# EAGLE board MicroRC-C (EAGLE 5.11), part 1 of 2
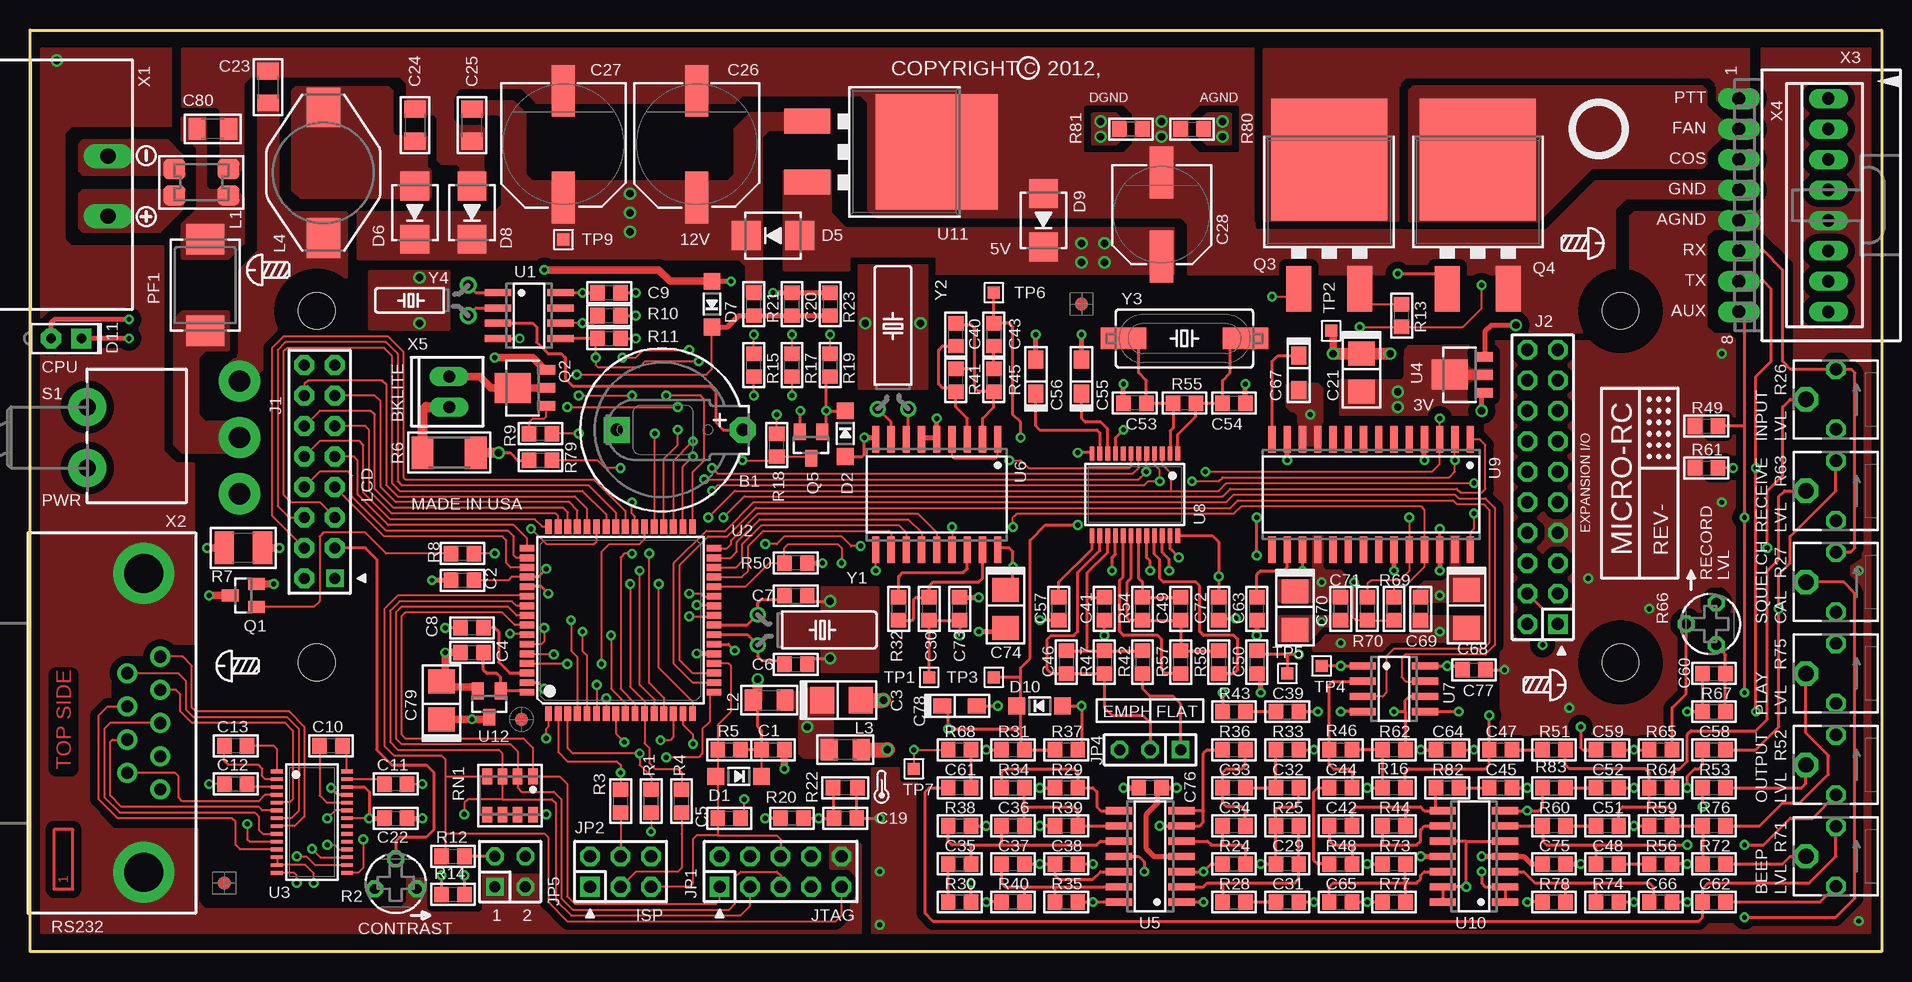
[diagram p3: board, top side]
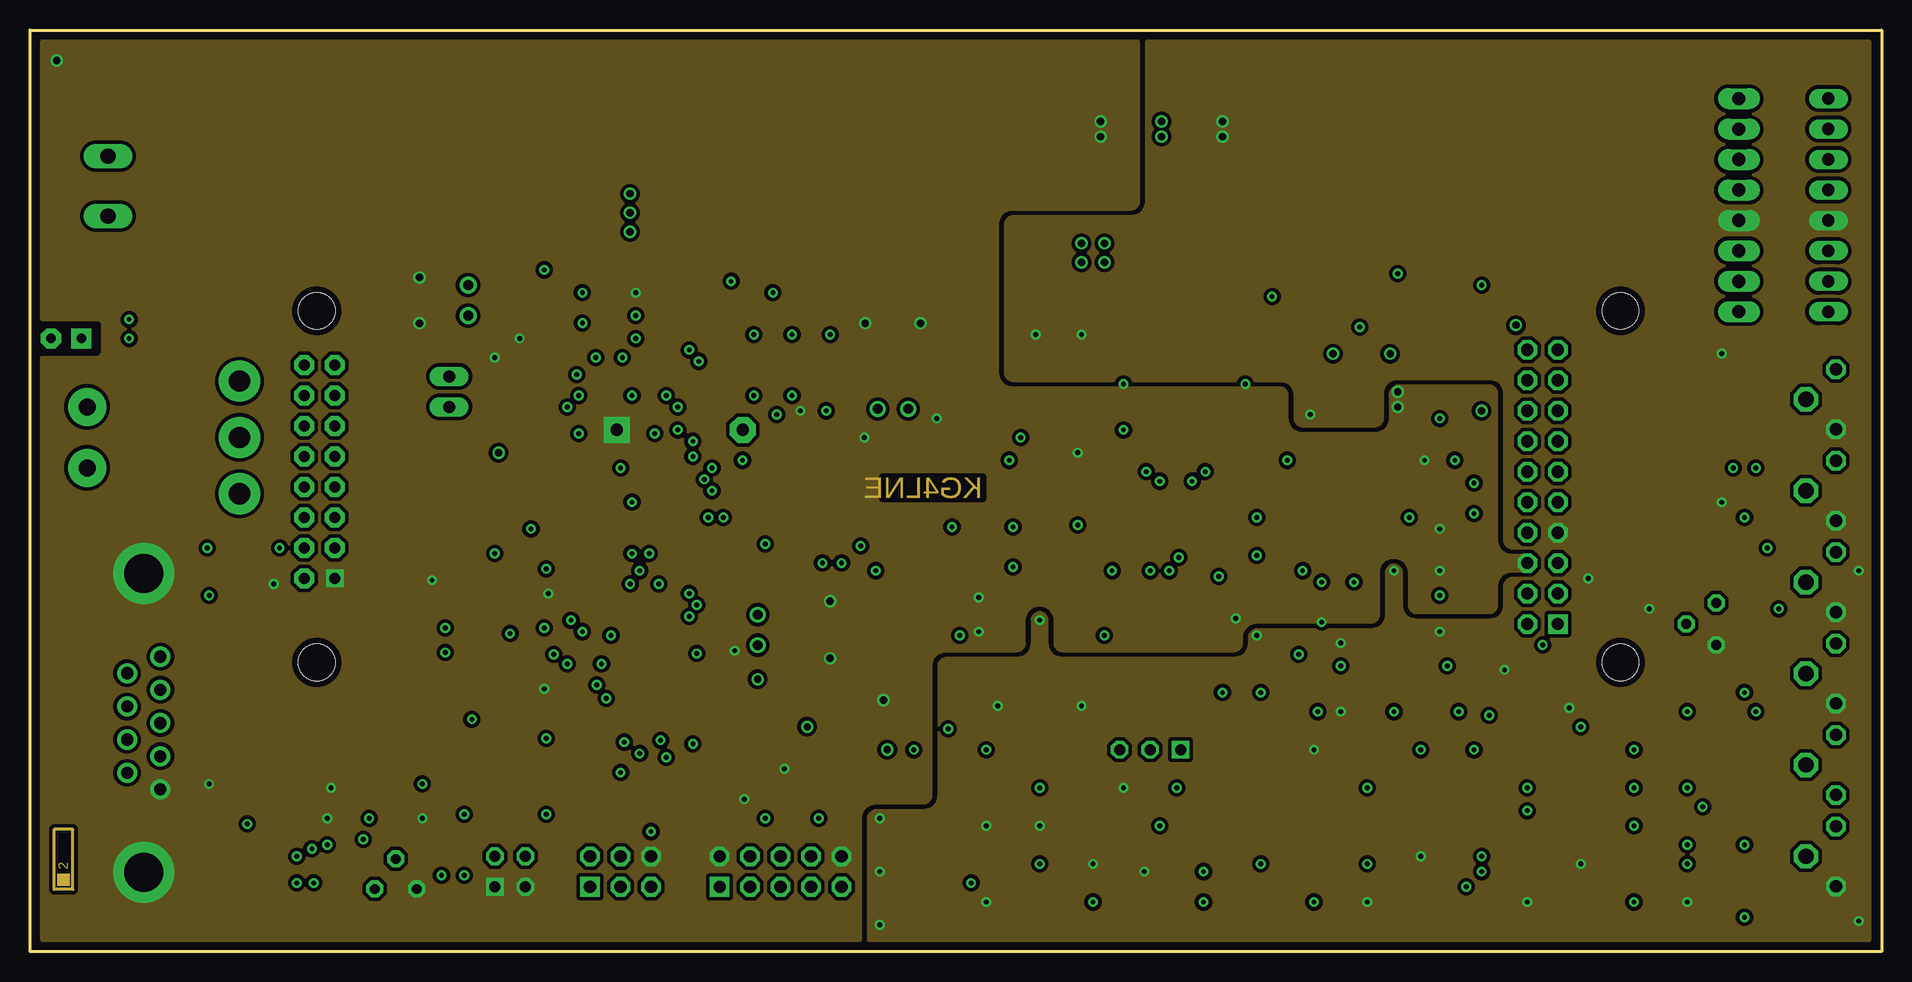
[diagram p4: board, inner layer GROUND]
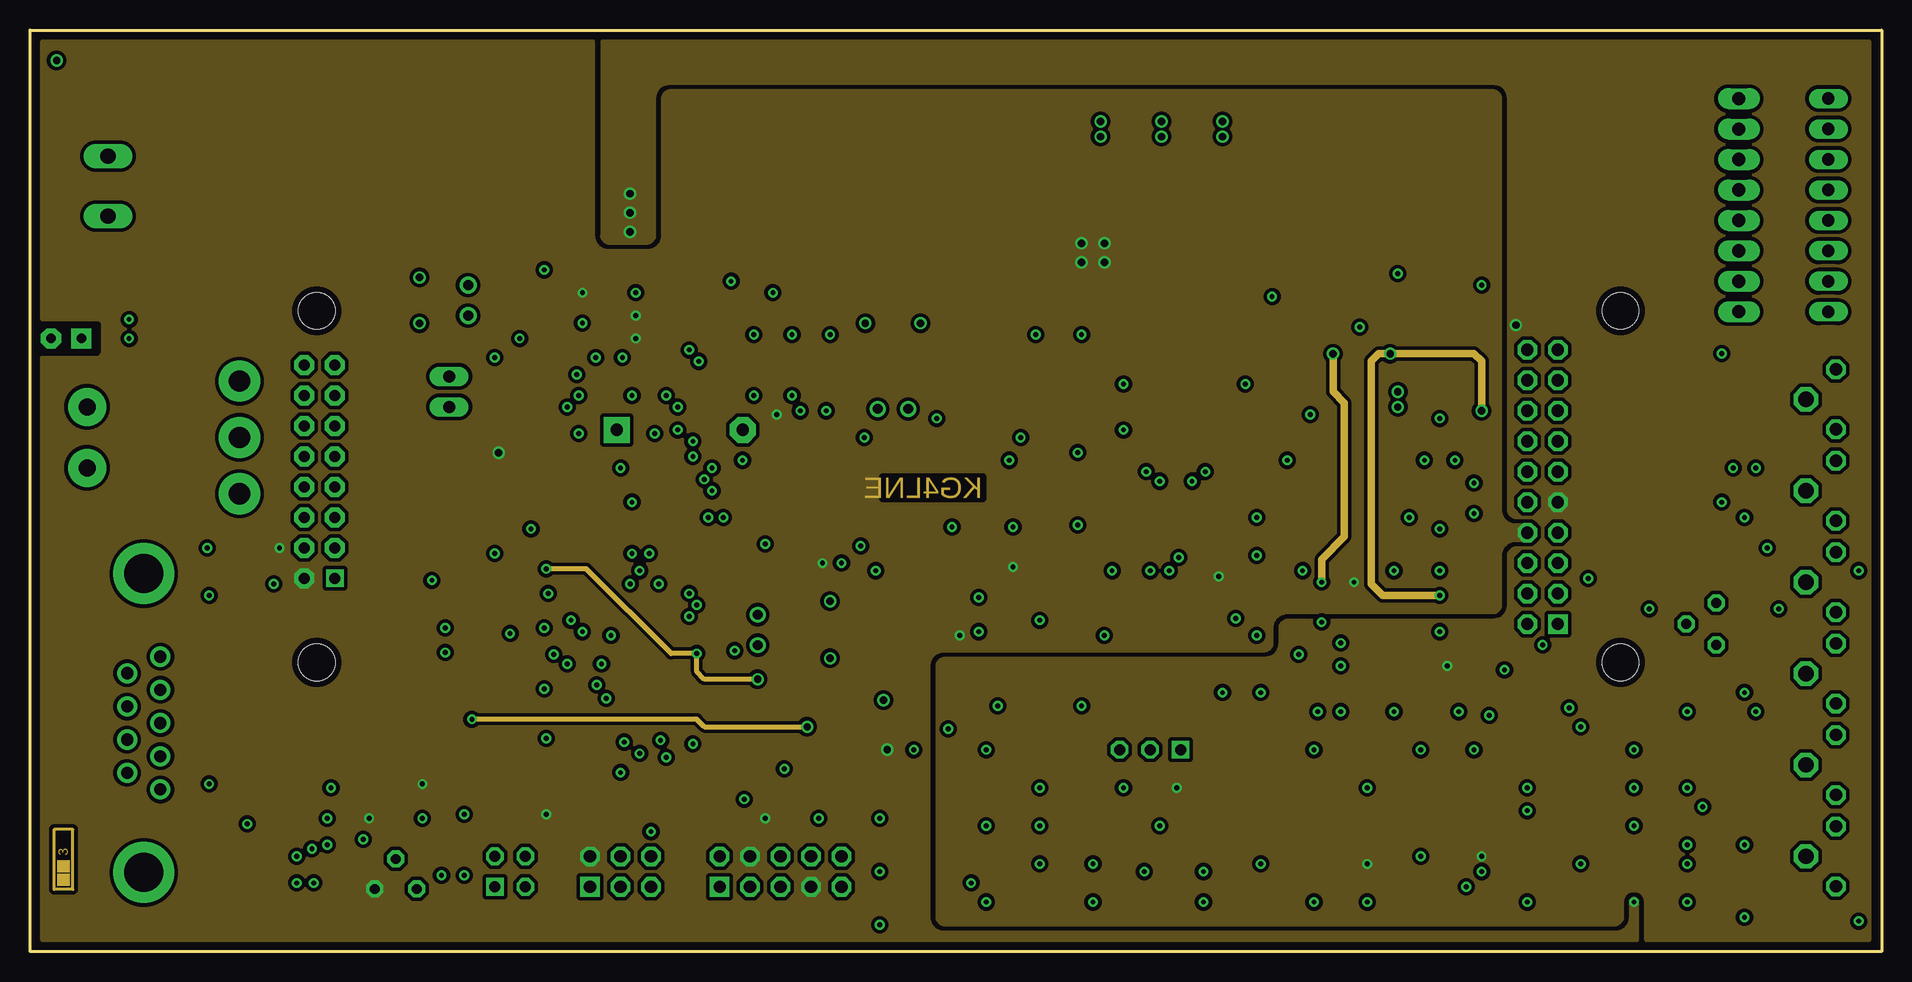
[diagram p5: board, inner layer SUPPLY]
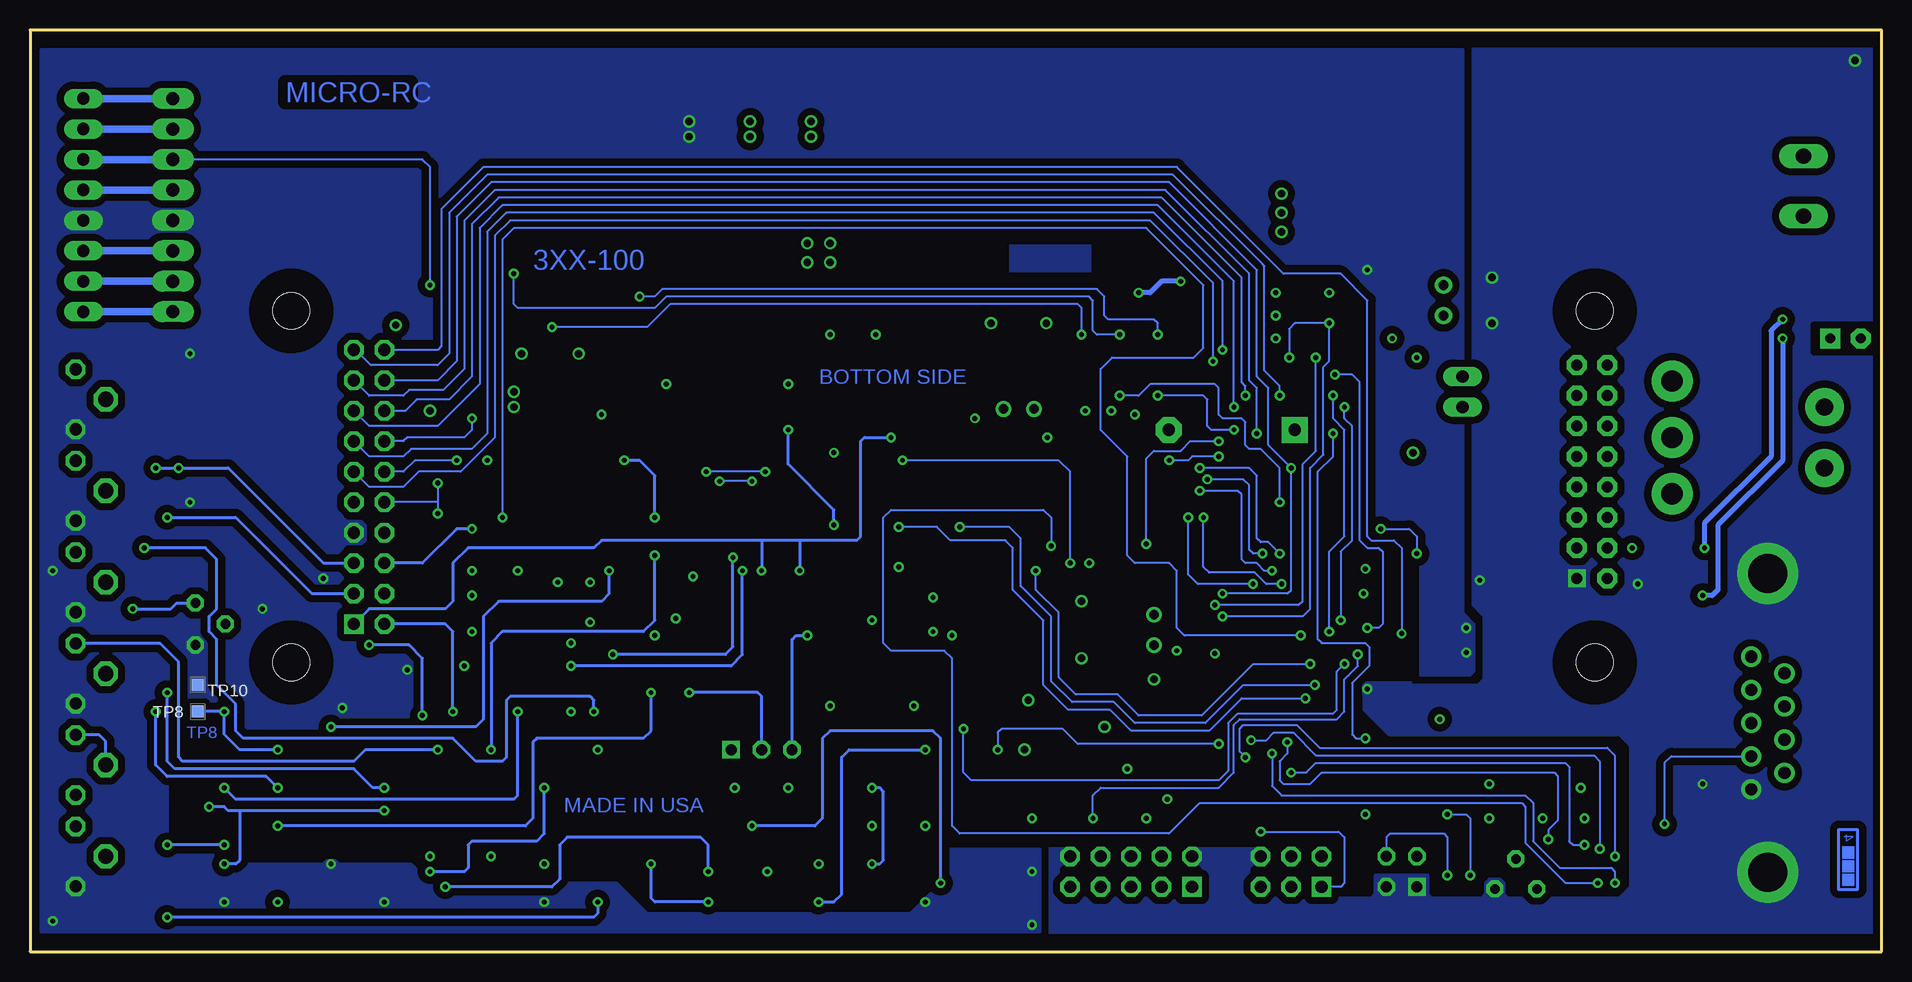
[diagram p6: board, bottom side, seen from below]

Size 154.31 x 76.83 mm. Coordinates in mm from the lower left corner, seen from the top.
Outline: 0,76.83 154.31,76.83 154.31,0 0,0 0,76.83
Copper layers (1*2+3*16): Top 0.035mm / dielectric 0.36mm / GROUND 0.035mm / dielectric 0.71mm / SUPPLY 0.035mm / dielectric 0.36mm / Bottom 0.035mm
Design rules "PRD_SN": minimum track width 2mil, minimum drill 16mil, track to track 8mil, track to pad 8mil, pad to pad 8mil, via to via 8mil, smd to smd 8mil, copper to edge 20mil, drill to drill 8mil, minimum pad ring 10mil, minimum via ring 8mil, stop-mask expansion 4mil, vias tented up to drill 32mil, thermal gap 24mil
Holes 0.41 mm at 198.11,50.4
Holes 0.61 mm at 198.11,45.32
Holes 0.81 mm at 198.11,40.24
Holes 0.91 mm at 198.11,35.16
Holes 1.02 mm at 198.11,30.08
Holes 1.09 mm at 198.11,25
Holes 1.27 mm at 198.11,19.92
Holes 1.42 mm at 198.11,14.84
Holes 1.78 mm at 198.11,9.76
Holes 3.05 mm at 198.11,4.68

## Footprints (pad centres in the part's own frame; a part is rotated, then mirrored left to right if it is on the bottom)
BR1225 = drill 1.016 pad 2.159 octagon: + 5.75,0 | drill 1.016 pad 2.159 square: - -4.75,0
C0805 = smd 1.2 x 1.3: 1 -0.953,0; 2 0.953,0
C3528/T = smd 2 x 2.2: + 1.587,0; - -1.587,0
C1206 = smd 1.4 x 1.8: 1 -1.329,0; 2 1.329,0
CSV-G = smd 4.318 x 1.93: + -4.445,0; - 4.445,0
CSV-E/F = smd 4.318 x 1.93: + -3.493,0; - 3.493,0
C3216/T = smd 1.5 x 1.27: + 1.429,0; - -1.429,0
SOD123 = smd 1.4 x 1.4: A 1.905,0; C -1.905,0
SMB = smd 2.4 x 2.4: A 2.223,0; C -2.223,0
LED535 = drill 0.813 pad 1.676 octagon: A -1.27,0 | drill 0.813 pad 1.676 square: K 1.27,0
DMC20261 = drill 0.914 pad 1.422 square: 1 2.54,-7.62 | drill 0.914 pad 1.676 octagon: 2 0,-7.62; 3 2.54,-5.08; 4 0,-5.08; 5 2.54,-2.54; 6 0,-2.54; 7 2.54,0; 8 0,0; 9 2.54,2.54; 10 0,2.54; 11 2.54,5.08; 12 0,5.08; 13 2.54,7.62; 14 0,7.62; 15 2.54,10.16; 16 0,10.16 | hole 3.048: 1.039,14.683; 1.039,-14.635; 109.674,-14.635; 109.674,14.682
MA10-2 = drill 1.016 square: 1 -11.43,-1.27 | drill 1.016 octagon: 2 -11.43,1.27; 3 -8.89,-1.27; 4 -8.89,1.27; 5 -6.35,-1.27; 6 -6.35,1.27; 7 -3.81,-1.27; 8 -3.81,1.27; 9 -1.27,-1.27; 10 -1.27,1.27; 11 1.27,-1.27; 12 1.27,1.27; 13 3.81,-1.27; 14 3.81,1.27; 15 6.35,-1.27; 16 6.35,1.27; 17 8.89,-1.27; 18 8.89,1.27; 19 11.43,-1.27; 20 11.43,1.27
AVR-JTAG-10 = drill 1.016 square: 1 -5.08,-1.27 | drill 1.016 octagon: 2 -5.08,1.27; 3 -2.54,-1.27; 4 -2.54,1.27; 5 0,-1.27; 6 0,1.27; 7 2.54,-1.27; 8 2.54,1.27; 9 5.08,-1.27; 10 5.08,1.27
AVR-ISP-6 = drill 1.016 square: 1 -2.54,-1.27 | drill 1.016 octagon: 2 -2.54,1.27; 3 0,-1.27; 4 0,1.27; 5 2.54,-1.27; 6 2.54,1.27
JP2 = drill 0.914 square: 1 -2.54,0 | drill 0.914 octagon: 2 0,0; 3 2.54,0
JP2Q = drill 0.914 square: 1 -1.27,-1.27 | drill 0.914 octagon: 2 -1.27,1.27; 3 1.27,-1.27; 4 1.27,1.27
CM1812 = smd 1.841 x 1.689: 1 -2.25,1.1; 2 -2.25,-1.1; 3 2.25,-1.1; 4 2.25,1.1
L1206 = smd 1.4 x 1.8: 1 -1.329,0; 2 1.329,0
PM-13 = smd 3.302 x 2.794: 1 -5.447,0; 2 5.447,0
SMD-7555 = smd 2.54 x 3.175: 1 -3.81,0; 2 3.81,0
SOT23@1 = smd 1 x 1.4: 1 -0.95,-1.1; 2 0.95,-1.1; 3 0,1.1
SOT89 = smd 0.8 x 1.5: 1 -1.5,-1.75; 2 0,-1.75; 3 1.5,-1.75 | smd 2.5 x 3: 4 0,1.05
D2PAK = smd 2.08 x 3.81: 1 -2.54,-8.255; 3 2.54,-8.255 | smd 9.652 x 10.16: 2 0,2.54
R0805 = smd 1.2 x 1.3: 1 -0.953,0; 2 0.953,0
EVM-L4G = drill 0.813 pad 1.422 octagon: 1 -1.75,-0.5; 2 0,2; 3 1.75,-0.5
R2010 = smd 1.8 x 2.7: 1 -2.223,0; 2 2.223,0
R1210 = smd 1.6 x 2.7: 1 -1.587,0; 2 1.587,0
R0805' = smd 1.2 x 1.3: 1 -1.016,0; 2 1.016,0
EVME-SIDE = drill 1.016 octagon: 1 -2.5,0; 3 2.5,0 | drill 1.27 octagon: 2 0,2.5
744-8 = smd 0.8 x 1.3: 1 -1.905,-1.587; 2 -0.635,-1.587; 3 0.635,-1.587; 4 1.905,-1.587; 5 1.905,1.587; 6 0.635,1.587; 7 -0.635,1.587; 8 -1.905,1.587
CK-A = drill 1.778 pad 3.429 round: 1 8.89,-4.699; 2 8.89,0; 3 8.89,4.699 | drill 1.422 pad 3.175 round: B1 -3.81,-2.54; B2 -3.81,2.54
TP10SQ = smd 1 x 1: TP 0,0
SMD-10SN = smd 1 x 1: TP 0,0
SO08 = smd 0.6 x 2.2: 1 -1.905,-2.6; 2 -0.635,-2.6; 3 0.635,-2.6; 4 1.905,-2.6; 5 1.905,2.6; 6 0.635,2.6; 7 -0.635,2.6; 8 -1.905,2.6
TQFP64-AEB = smd 1.194 x 0.559: 1 -7.8,6; 2 -7.8,5.2; 3 -7.8,4.4; 4 -7.8,3.6; 5 -7.8,2.8; 6 -7.8,2; 7 -7.8,1.2; 8 -7.8,0.4; 9 -7.8,-0.4; 10 -7.8,-1.2; 11 -7.8,-2; 12 -7.8,-2.8; 13 -7.8,-3.6; 14 -7.8,-4.4; 15 -7.8,-5.2; 16 -7.8,-6; 33 7.8,-6; 34 7.8,-5.2; 35 7.8,-4.4; 36 7.8,-3.6; 37 7.8,-2.8; 38 7.8,-2; 39 7.8,-1.2; 40 7.8,-0.4; 41 7.8,0.4; 42 7.8,1.2; 43 7.8,2; 44 7.8,2.8; 45 7.8,3.6; 46 7.8,4.4; 47 7.8,5.2; 48 7.8,6 | smd 0.559 x 1.194: 17 -6,-7.8; 18 -5.2,-7.8; 19 -4.4,-7.8; 20 -3.6,-7.8; 21 -2.8,-7.8; 22 -2,-7.8; 23 -1.2,-7.8; 24 -0.4,-7.8; 25 0.4,-7.8; 26 1.2,-7.8; 27 2,-7.8; 28 2.8,-7.8; 29 3.6,-7.8; 30 4.4,-7.8; 31 5.2,-7.8; 32 6,-7.8; 49 6,7.8; 50 5.2,7.8; 51 4.4,7.8; 52 3.6,7.8; 53 2.8,7.8; 54 2,7.8; 55 1.2,7.8; 56 0.4,7.8; 57 -0.4,7.8; 58 -1.2,7.8; 59 -2,7.8; 60 -2.8,7.8; 61 -3.6,7.8; 62 -4.4,7.8; 63 -5.2,7.8; 64 -6,7.8
TSSOP28 = smd 0.305 x 0.991: 1 -4.225,-2.918; 2 -3.575,-2.918; 3 -2.925,-2.918; 4 -2.275,-2.918; 5 -1.625,-2.918; 6 -0.975,-2.918; 7 -0.325,-2.918; 8 0.325,-2.918; 9 0.975,-2.918; 10 1.625,-2.918; 11 2.275,-2.918; 12 2.925,-2.918; 13 3.575,-2.918; 14 4.225,-2.918; 15 4.225,2.918; 16 3.575,2.918; 17 2.925,2.918; 18 2.275,2.918; 19 1.625,2.918; 20 0.975,2.918; 21 0.325,2.918; 22 -0.325,2.918; 23 -0.975,2.918; 24 -1.625,2.918; 25 -2.275,2.918; 26 -2.925,2.918; 27 -3.575,2.918; 28 -4.225,2.918
SOT89-4 = smd 0.8 x 1.5: 1 -1.5,-1.75; 2 0,-1.75; 3 1.5,-1.75 | smd 2.5 x 3: 4 0,1.05
SO14 = smd 0.6 x 2.2: 1 -3.81,-2.6; 2 -2.54,-2.6; 3 -1.27,-2.6; 4 0,-2.6; 5 1.27,-2.6; 6 2.54,-2.6; 7 3.81,-2.6; 8 3.81,2.6; 9 2.54,2.6; 10 1.27,2.6; 11 0,2.6; 12 -1.27,2.6; 13 -2.54,2.6; 14 -3.81,2.6
SO18W = smd 0.6 x 2.2: 1 -5.08,-4.6; 2 -3.81,-4.6; 3 -2.54,-4.6; 4 -1.27,-4.6; 5 0,-4.6; 6 1.27,-4.6; 7 2.54,-4.6; 8 3.81,-4.6; 9 5.08,-4.6; 10 5.08,4.6; 11 3.81,4.6; 12 2.54,4.6; 13 1.27,4.6; 14 0,4.6; 15 -1.27,4.6; 16 -2.54,4.6; 17 -3.81,4.6; 18 -5.08,4.6
SSOP24 = smd 0.4 x 1.2: 1 -3.575,-3.42; 2 -2.925,-3.42; 3 -2.275,-3.42; 4 -1.625,-3.42; 5 -0.975,-3.42; 6 -0.325,-3.42; 7 0.325,-3.42; 8 0.975,-3.42; 9 1.625,-3.42; 10 2.275,-3.42; 11 2.925,-3.42; 12 3.575,-3.42; 13 3.575,3.42; 14 2.925,3.42; 15 2.275,3.42; 16 1.625,3.42; 17 0.975,3.42; 18 0.325,3.42; 19 -0.325,3.42; 20 -0.975,3.42; 21 -1.625,3.42; 22 -2.275,3.42; 23 -2.925,3.42; 24 -3.575,3.42
SO28W = smd 0.6 x 2.2: 1 -8.255,-4.6; 2 -6.985,-4.6; 3 -5.715,-4.6; 4 -4.445,-4.6; 5 -3.175,-4.6; 6 -1.905,-4.6; 7 -0.635,-4.6; 8 0.635,-4.6; 9 1.905,-4.6; 10 3.175,-4.6; 11 4.445,-4.6; 12 5.715,-4.6; 13 6.985,-4.6; 14 8.255,-4.6; 15 8.255,4.6; 16 6.985,4.6; 17 5.715,4.6; 18 4.445,4.6; 19 3.175,4.6; 20 1.905,4.6; 21 0.635,4.6; 22 -0.635,4.6; 23 -1.905,4.6; 24 -3.175,4.6; 25 -4.445,4.6; 26 -5.715,4.6; 27 -6.985,4.6; 28 -8.255,4.6
SOT23 = smd 1 x 1.4: 1 -0.95,-1.1; 2 0.95,-1.1; 3 0,1.1
951-2 = drill 1.27 pad 1.93 long: 1 -2.5,0; 2 2.5,0
NC182M9 = drill 1.016 pad 1.676 round: 1 -5.537,2.769; 2 -2.769,2.769; 3 0,2.769; 4 2.769,2.769; 5 5.537,2.769; 6 -4.153,0; 7 -1.384,0; 8 1.384,0; 9 4.153,0 | drill 3.251 pad 5.08 round: G1 12.459,1.384; G2 -12.459,1.384
70553-08 = drill 1.092 long: 1 -8.89,-7.62; 2 -6.35,-7.62; 3 -3.81,-7.62; 4 -1.27,-7.62; 5 1.27,-7.62; 6 3.81,-7.62; 7 6.35,-7.62; 8 8.89,-7.62
MTA08-100 = drill 1.016 long: 1 8.89,0; 2 6.35,0; 3 3.81,0; 4 1.27,0; 5 -1.27,0; 6 -3.81,0; 7 -6.35,0; 8 -8.89,0
MTA-100-2V = drill 1.016 long: 1 -1.27,0; 2 1.27,0
TC38H = drill 0.813 round: 1 -1.27,0; 2 1.27,0
TC310H = drill 0.813 round: 1 -1.27,0; 2 1.27,0
SM49 = smd 3.81 x 1.778: 1 -5.08,0; 2 5.08,0
TC26H = drill 0.813 pad 1.422 round: 1 -1.27,0; 2 1.27,0

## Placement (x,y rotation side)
B1  BR1225A/HB  [BR1225]  53.66,43.5 0 top
C1  1uF  [C0805]  61.91,16.83 0 top
C2  0.1uF  [C0805]  36.04,30.96 180 top
C3  10uF  [C3528/T]  67.63,20.95 180 top
C4  10uF  [C0805]  36.83,24.92 0 top
C5  0.01uF  [C0805]  58.26,11.11 0 top
C6  22pF  [C0805]  63.82,23.95 0 top
C7  22pF  [C0805]  63.82,29.67 0 top
C8  0.1uF  [C0805]  36.83,26.99 180 top
C9  0.1uF  [C0805]  48.26,54.93 0 top
C10  0.1uF  [C0805]  25.08,17.14 180 top
C11  0.47uF  [C0805]  30.48,13.97 180 top
C12  0.47uF  [C0805]  17.14,13.97 0 top
C13  0.47uF  [C0805]  17.14,17.14 180 top
C19  0.1uF  [C0805]  67.94,11.11 0 top
C20  0.1uF  [C0805]  63.5,53.97 90 top
C21  10uF  [C3528/T]  110.97,48.26 90 top
C22  1uF  [C0805]  30.48,11.11 0 top
C23  0.1uF  [C1206]  19.84,72.07 90 top
C24  0.1uF  [C1206]  32.07,68.9 90 top
C25  0.1uF  [C1206]  36.83,68.9 270 top
C26  470uF  [CSV-G]  55.56,67.31 90 top
C27  470uF  [CSV-G]  44.45,67.31 90 top
C28  100uF  [CSV-E/F]  94.3,61.44 90 top
C29  100pF  [C0805]  104.78,7.3 180 top
C30  0.1uF  [C0805]  74.93,28.57 270 top
C31  0.1uF  [C0805]  104.78,4.13 180 top
C32  1500pF  [C0805]  104.78,13.65 180 top
C33  1500pF  [C0805]  100.33,13.65 180 top
C34  1500pF  [C0805]  100.33,10.48 180 top
C35  0.047uF  [C0805]  77.47,7.3 0 top
C36  470pF  [C0805]  81.92,10.48 0 top
C37  470pF  [C0805]  81.92,7.3 180 top
C38  0.047uF  [C0805]  86.36,7.3 180 top
C39  1uF  [C0805]  104.78,20 0 top
C40  0.001uF  [C0805]  77.15,51.43 90 top
C41  0.0068uF  [C0805]  89.53,28.57 270 top
C42  1500pF  [C0805]  109.22,10.48 0 top
C43  0.1uF  [C0805]  80.33,51.43 270 top
C44  1uF  [C0805]  109.22,13.65 180 top
C45  1uF  [C0805]  122.56,13.65 0 top
C46  100pF  [C0805]  86.36,24.13 270 top
C47  1uF  [C0805]  122.56,16.83 0 top
C48  560pF  [C0805]  131.44,7.3 0 top
C49  100pF  [C0805]  95.89,28.57 90 top
C50  1uF  [C0805]  102.23,24.13 270 top
C51  10uF  [C0805]  131.44,10.48 180 top
C52  1uF  [C0805]  131.44,13.65 0 top
C53  33pF  [C0805]  92.08,45.72 180 top
C54  33pF  [C0805]  100.33,45.72 0 top
C55  0.1uF  [C3216/T]  87.63,47.94 270 top
C56  2.2uF  [C3216/T]  83.82,47.94 270 top
C57  0.1uF  [C0805]  85.72,28.57 270 top
C58  1uF  [C0805]  140.34,16.83 0 top
C59  1uF  [C0805]  131.44,16.83 180 top
C60  4700pF  [C0805]  140.34,23.18 0 top
C61  1uF  [C0805]  77.47,13.65 180 top
C62  0.001uF  [C0805]  140.34,4.13 0 top
C63  0.1uF  [C0805]  102.23,28.57 90 top
C64  1uF  [C0805]  118.11,16.83 0 top
C65  1uF  [C0805]  109.22,4.13 0 top
C66  1uF  [C0805]  135.89,4.13 0 top
C67  1uF  [C3216/T]  105.73,48.26 90 top
C68  22uF  [C3528/T]  119.7,28.57 90 top
C69  0.1uF  [C0805]  115.89,28.57 270 top
C70  22uF  [C3528/T]  105.41,28.42 90 top
C71  0.1uF  [C0805]  109.22,28.57 270 top
C72  0.1uF  [C0805]  99.06,28.57 270 top
C73  0.1uF  [C0805]  77.47,28.57 90 top
C74  22uF  [C3528/T]  81.28,28.57 90 top
C75  0.1uF  [C0805]  127,7.3 0 top
C76  0.1uF  [C0805]  93.34,13.65 180 top
C77  0.1uF  [C0805]  120.33,23.49 0 top
C78  0.1uF  [C3216/T]  77.47,20.48 180 top
C79  10uF  [C3528/T]  34.29,20.96 270 top
C80  0.01uF  [C1206]  15.24,68.58 0 top
D1  BAV16W-7-F  [SOD123]  59.05,14.6 180 top
D2  5.1V  [SOD123]  67.94,43.18 270 top
D5  S1GB-13  [SMB]  61.91,59.69 0 top
D6  S1GB-13  [SMB]  32.07,61.59 90 top
D7  BZT52C5V1-7-F  [SOD123]  56.83,53.97 90 top
D8  18V  [SMB]  36.83,61.59 90 top
D9  S1GB-13  [SMB]  84.45,60.96 90 top
D10  BZT52C5V1-7-F  [SOD123]  84.14,20.48 0 top
D11  RED  [LED535]  3.02,51.12 0 top
FIDUCIAL1  FIDUCIAL-G10S  [G10S]  16.19,5.71 0 top
FIDUCIAL2  FIDUCIAL-G10S  [G10S]  87.63,53.97 0 top
FIDUCIAL3  FIDUCIAL-G10  [G10]  40.96,19.37 0 top
J1  DMC20261  [DMC20261]  22.86,38.73 0 top
J2  [MA10-2]  126.05,38.73 90 top
JP1  AVR-JTAG-10  [AVR-JTAG-10]  62.55,6.67 0 top
JP2  AVR-ISP-6  [AVR-ISP-6]  49.21,6.67 0 top
JP4  [JP2]  93.34,16.83 180 top
JP5  [JP2Q]  40.01,6.67 0 top
L1  CM1812  [CM1812]  14.29,64.13 0 top
L2  0.1uH  [L1206]  61.59,20.95 180 top
L3  FB-M1331  [L1206]  67.94,16.83 0 top
L4  10uH  [PM-13]  24.45,64.93 90 top
PF1  MF-SM030-2  [SMD-7555]  14.61,55.56 270 top
Q1  MMBTA05LT1G  [SOT23@1]  17.78,29.69 90 top
Q2  ZXMN6A07Z  [SOT89]  41.27,46.99 90 top
Q3  IRF614SPBF  [D2PAK]  108.27,63.5 0 top
Q4  IRF614SPBF  [D2PAK]  120.65,63.5 0 top
Q5  MMBTA05LT1G  [SOT23@1]  65.09,42.23 180 top
R1  47.5R  [R0805]  51.75,12.54 90 top
R2  10K  [EVM-L4G]  30.48,5.71 0 top
R3  47.5R  [R0805]  49.21,12.54 90 top
R4  47.5R  [R0805]  54.29,12.54 90 top
R5  10K  [R0805]  58.26,16.83 0 top
R6  48.7R  [R2010]  34.92,41.59 180 top
R7  464R  [R1210]  17.78,33.65 180 top
R8  4.75K  [R0805]  36.04,33.18 180 top
R9  4.75K  [R0805]  42.55,43.18 180 top
R10  10K  [R0805]  48.26,53.02 0 top
R11  10K  [R0805]  48.26,51.12 0 top
R12  47.5R  [R0805]  35.24,7.94 0 top
R13  100K  [R0805]  114.3,53.02 90 top
R14  47.5R  [R0805]  35.24,4.76 0 top
R15  4.75K  [R0805]  60.33,48.89 90 top
R16  1M  [R0805]  113.67,13.65 180 top
R17  4.75K  [R0805]  63.5,48.89 90 top
R18  10K  [R0805]  62.23,42.23 90 top
R19  4.75K  [R0805]  66.67,48.89 90 top
R20  100K  [R0805]  63.5,11.11 180 top
R21  62K  [R0805]  60.33,53.97 90 top
R22  NCP21WF104J03RA  [R0805']  67.94,13.65 180 top
R23  22K  [R0805]  66.67,53.97 270 top
R24  91.0K  [R0805]  100.33,7.3 0 top
R25  10K  [R0805]  104.78,10.48 180 top
R26  10K  [EVME-SIDE]  150.5,46.04 90 top
R27  10K  [EVME-SIDE]  150.5,30.8 90 top
R28  10K  [R0805]  100.33,4.13 180 top
R29  332K  [R0805]  86.36,13.65 0 top
R30  4.75K  [R0805]  77.47,4.13 0 top
R31  22K  [R0805]  81.92,16.83 180 top
R32  301K  [R0805]  72.39,28.57 270 top
R33  4.75K  [R0805]  104.78,16.83 180 top
R34  100K  [R0805]  81.92,13.65 0 top
R35  150K  [R0805]  86.36,4.13 180 top
R36  5.62K  [R0805]  100.33,16.83 180 top
R37  100K  [R0805]  86.36,16.83 0 top
R38  8.25K  [R0805]  77.47,10.48 0 top
R39  10K  [R0805]  86.36,10.48 180 top
R40  10K  [R0805]  81.92,4.13 180 top
R41  100K  [R0805]  77.15,47.62 90 top
R42  11.3K  [R0805]  92.71,24.13 270 top
R43  10K  [R0805]  100.33,20 0 top
R44  22K  [R0805]  113.67,10.48 0 top
R45  100K  [R0805]  80.33,47.62 270 top
R46  1M  [R0805]  109.22,16.83 0 top
R47  93.1K  [R0805]  89.53,24.13 270 top
R48  22K  [R0805]  109.22,7.3 0 top
R49  100K  [R0805]  139.7,43.81 0 top
R50  10K  [R0805]  63.82,32.38 180 top
R51  22K  [R0805]  127,16.83 0 top
R52  200K  [EVME-SIDE]  150.5,15.56 90 top
R53  33.2K  [R0805]  140.34,13.65 180 top
R54  10K  [R0805]  92.71,28.57 90 top
R55  1M  [R0805]  96.2,45.72 180 top
R56  10K  [R0805]  135.89,7.3 0 top
R57  10K  [R0805]  95.89,24.13 90 top
R58  10K  [R0805]  99.06,24.13 90 top
R59  22K  [R0805]  135.89,10.48 0 top
R60  33.2K  [R0805]  127,10.48 180 top
R61  100K  [R0805]  139.7,40.32 0 top
R62  1M  [R0805]  113.67,16.83 180 top
R63  10K  [EVME-SIDE]  150.5,38.42 90 top
R64  22K  [R0805]  135.89,13.65 180 top
R65  10K  [R0805]  135.89,16.83 0 top
R66  10K  [EVM-L4G]  140.02,27.3 90 top
R67  10K  [R0805]  140.34,20 0 top
R68  100K  [R0805]  77.47,16.83 0 top
R69  10K  [R0805]  113.67,28.57 270 top
R70  10K  [R0805]  111.44,28.57 270 top
R71  10K  [EVME-SIDE]  150.5,7.94 90 top
R72  22K  [R0805]  140.34,7.3 0 top
R73  100K  [R0805]  113.67,7.3 180 top
R74  100K  [R0805]  131.44,4.13 0 top
R75  10K  [EVME-SIDE]  150.5,23.18 90 top
R76  22K  [R0805]  140.34,10.48 180 top
R77  100K  [R0805]  113.67,4.13 0 top
R78  100K  [R0805]  127,4.13 0 top
R79  10K  [R0805]  42.55,40.96 180 top
R80  0R  [R0805]  96.84,68.58 0 top
R81  0R  [R0805]  91.76,68.58 180 top
R82  1.00K  [R0805]  118.11,13.65 0 top
R83  1.00K  [R0805]  127,13.65 0 top
RN1  10K  [744-8]  40.01,13.02 180 top
S1  CK-A  [CK-A]  8.57,42.86 0 top
TP1  TPTP10SQ  [TP10SQ]  74.93,22.86 270 top
TP2  TPTP10SQ  [TP10SQ]  108.43,51.75 180 top
TP3  TPTP10SQ  [TP10SQ]  80.33,22.86 270 top
TP4  TPTP10SQ  [TP10SQ]  107.63,23.81 90 top
TP5  TPTP10SQ  [TP10SQ]  104.78,23.18 90 top
TP6  TPTP10SQ  [TP10SQ]  80.33,54.93 90 top
TP7  TPTP10SQ  [TP10SQ]  73.66,15.24 270 top
TP8  TPS-SMD-10SN  [SMD-10SN]  140.34,20 180 bottom
TP9  TPTP10SQ  [TP10SQ]  44.45,59.37 0 top
TP10  TPS-SMD-10SN  [SMD-10SN]  140.34,22.22 180 bottom
U1  DS1307Z  [SO08]  41.59,53.02 270 top
U2  MEGA1281/2561  [TQFP64-AEB]  49.21,27.62 90 top
U3  MAX3243IPWR  [TSSOP28]  23.5,10.79 270 top
U4  L78L33ACUTR  [SOT89-4]  119.38,48.1 90 top
U5  LM324D  [SO14]  93.34,7.94 90 top
U6  CM8870CS  [SO18W]  75.56,38.1 180 top
U7  MAX323CSA  [SO08]  113.67,21.91 270 top
U8  MX828DS  [SSOP24]  92.08,38.1 180 top
U9  ISD4002S  [SO28W]  111.76,38.1 180 top
U10  TL084D  [SO14]  120.33,7.94 90 top
U11  L7805ACD2T  [D2PAK]  73.03,66.67 270 top
U12  AD158X  [SOT23]  38.26,20.64 180 top
U$6  [ICON_ATTR_COPYRIGHT]  71.75,73.02 0 top
U$7  [LAYER_CHECK-4]  3.17,5.71 90 top
U$60  [FIELD_ATTR_DATECODE5_RESTRICT]  72.07,57.15 0 bottom
U$74  [ICON_SIDE_BOTTOM]  88.58,47.31 0 top
U$75  [ICON_SIDE_TOP]  3.43,15.18 90 top
U$100  [ICON_ATTR_REV-M]  130.81,68.58 0 top
U$102  [FAB_8X14]  not placed on the board
U$105  [FAB_DOCFIELD]  not placed on the board
U$112  [ICON_TEMP]  70.96,13.02 0 top
U$123  [ICON_MINUS]  9.68,66.36 90 top
U$124  3.0250  [FAB_ARROW_LINE025]  -1.27,0 180 top
U$125  [ICON_PLUS]  9.68,61.28 0 top
U$128  0,0  [FAB_ARROW_LINE025]  0,78.1 90 top
U$132  2.7125  [FAB_CONST_LINE050]  154.31,7.94 0 top
U$133  [ICON_MSCREW-S]  129.86,59.05 270 top
U$136  0,0  [FAB_ARROW_LINE025]  -1.27,76.83 180 top
U$138  6.0750  [FAB_ARROW_LINE025]  154.31,78.1 90 top
U$139  0.5750  [FAB_CONST_LINE050]  154.31,62.23 0 top
U$140  1.2125  [FAB_CONST_LINE050]  154.31,46.04 0 top
U$141  1.5125  [FAB_CONST_LINE050]  154.31,38.42 0 top
U$142  1.8125  [FAB_CONST_LINE050]  154.31,30.8 0 top
U$143  2.1125  [FAB_CONST_LINE050]  154.31,23.18 0 top
U$144  2.4125  [FAB_CONST_LINE050]  154.31,15.56 0 top
U$145  1.3375  [FAB_CONST_LINE050]  0,42.86 180 top
U$146  2.2750  [FAB_CONST_LINE050]  0,19.05 180 top
U$230  [ICON_PIN1_B]  127.64,25.4 270 top
U$235  [ICON_PIN1_B]  27.3,31.11 0 top
U$239  [ICON_MSCREW-S]  126.68,22.22 270 top
U$240  [ICON_ARROW-T]  33.34,3.02 270 top
U$241  [ICON_ARROW-T]  138.43,31.75 0 top
U$280  [ICON_PIN1_B]  46.67,3.49 270 top
U$281  [ICON_PIN1_B]  57.47,3.49 270 top
U$282  [ICON_MSCREW-S]  16.83,23.81 90 top
U$283  [ICON_MSCREW-S]  19.37,56.83 90 top
X1  EDSTLZ951/2  [951-2]  6.51,63.82 270 top
X2  182-009-112-531  [NC182M9]  8.1,19.05 270 top
X3  70553-0007  [70553-08]  150.02,62.23 270 top
X4  640454-8  [MTA08-100]  149.86,62.23 90 top
X5  640454-2  [MTA-100-2V]  34.92,46.67 90 top
Y1  16.000 MHz  [TC38H]  60.64,26.81 270 top
Y2  3.579 MHZ  [TC310H]  71.91,45.24 0 top
Y3  4.032MHZ  [SM49]  96.2,51.12 0 top
Y4  32.678 kHz  [TC26H]  36.51,54.29 90 top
